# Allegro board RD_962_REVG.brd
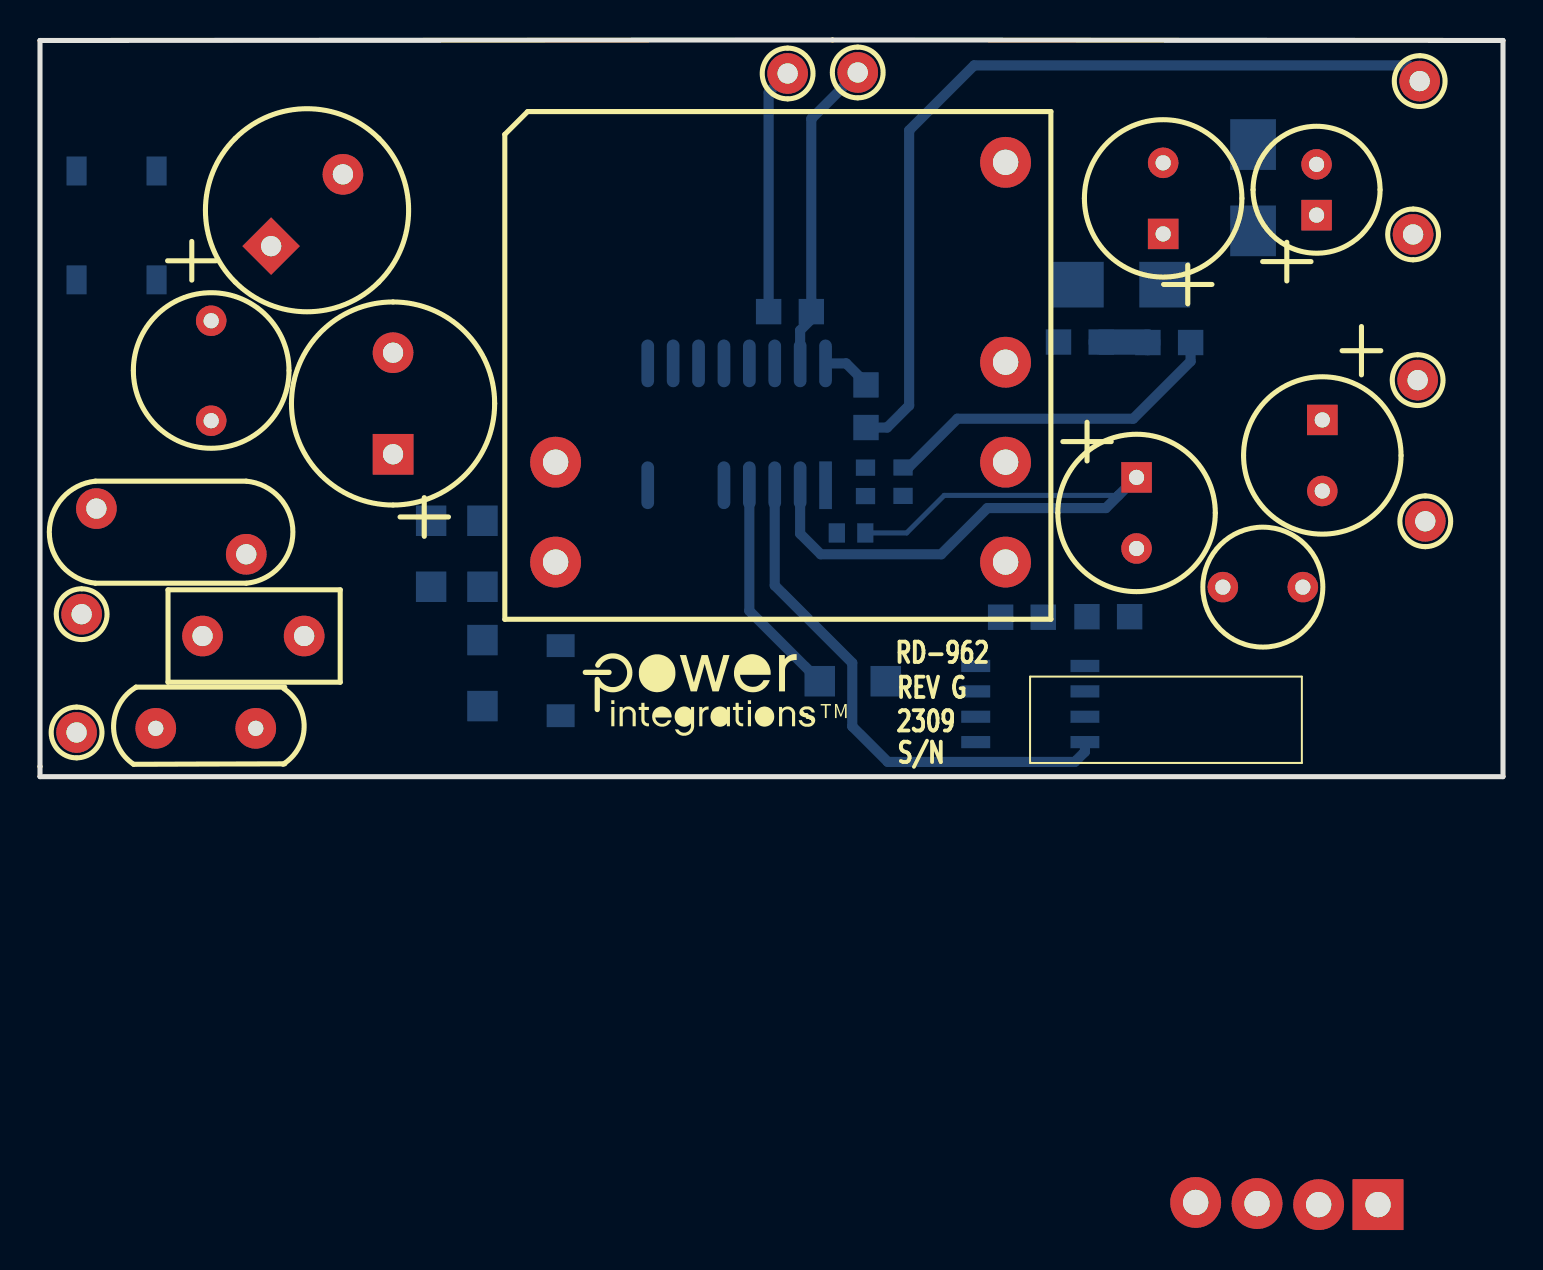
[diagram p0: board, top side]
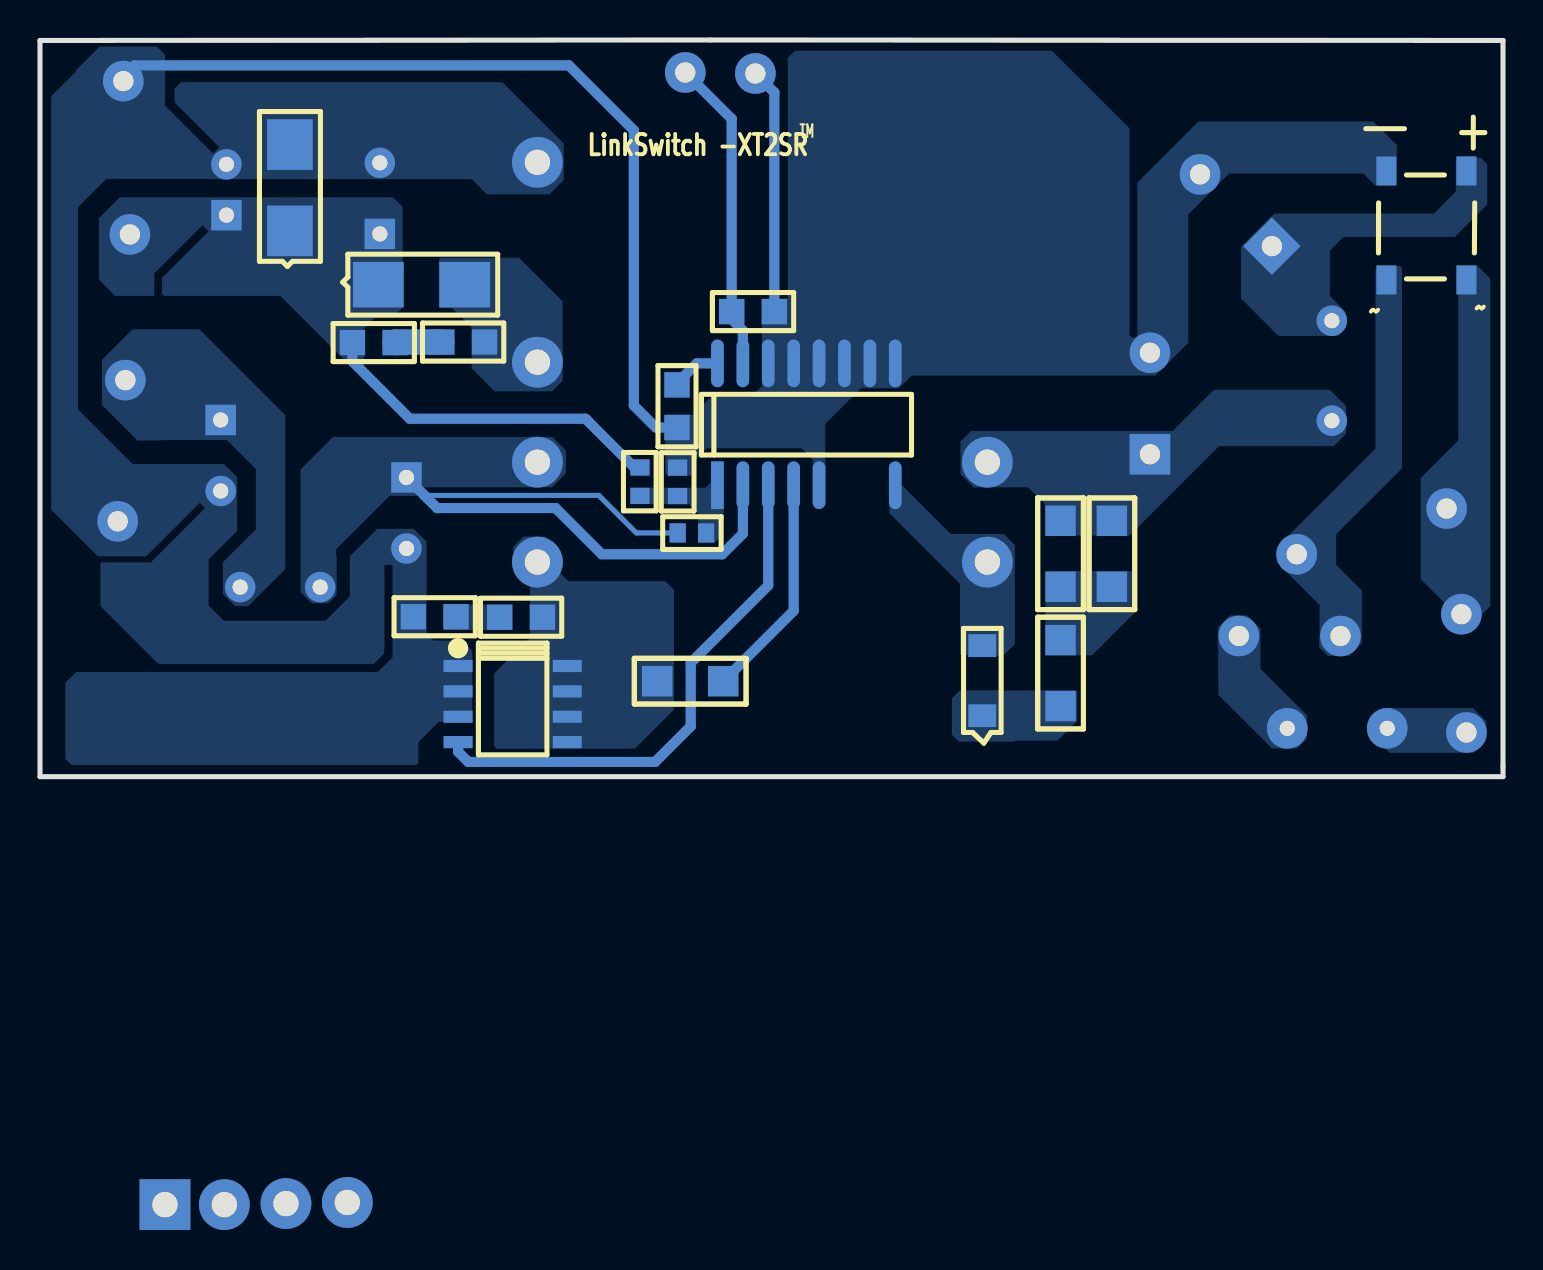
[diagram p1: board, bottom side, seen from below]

Outline 73.15 x 36.86 mm; copper layers: TOP, BOTTOM. Coordinates in mm from the lower left corner of the outline.
Outline path: 0,36.83 0,0 73.15,0 73.15,36.83 39.62,36.86 0,36.83

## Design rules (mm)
constraint set DEFAULT: min track width 0.508

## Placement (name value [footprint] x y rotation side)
BR1  ABS210-13  [PISMD_SOPA-4]  1.83 30.3 180 bottom
C1  15 uF  [PIPOLCAPCYLD400LS200040]  11.56 26.54 45 top
C2  15 uF  [PIPOLCAPCYLD400LS200040]  17.65 16.13 90 top
C3  1000 pF  [PISMC1206]  22.12 12.8 270 bottom
C4  4.7 uF  [PISMC0805]  41.3 19.6 270 bottom
C5  2.2 uF  [PISMC0805]  36.43 23.27 0 bottom
C6  1.5 nF  [PISMC0805]  52.35 8 0 bottom
C7  1000 uF  [PIPOLCAPCLYD320LS140030]  56.16 27.15 90 top
C9  100 uF  [PIPOLCAPCYLD250LS100030]  63.83 28.09 90 top
C10  680  uF  [PIPOLCAPCLYD320LS140030]  54.83 14.97 270 top
C11  680  uF  [PIPOLCAPCLYD320LS140030]  64.12 17.85 270 top
C12  1 nF  [PISMC0805]  55.4 21.72 0 bottom
D1  S1MLHRVG  [PI_SM_SOD-123_12]  26.04 3.05 90 bottom
D2  STPS2150A  [PISMDO214AC12]  56.24 24.61 180 bottom
F1  2 A  [PI_RST_MICROFUSE]  13.21 7.04 180 top
GND  BLK  [PITPKEYSTONE100X100]  37.38 35.18 0 top
GND1  BLK  [PITPKEYSTONE100X100]  68.99 34.8 0 top
GND2  BLK  [PITPKEYSTONE100X100]  69.27 12.78 0 top
L  BLK  [PITPKEYSTONE100X100]  1.83 2.21 0 top
L1  330 uH  [PICHOKETOKINVD345H453LS197D030]  8.56 22.81 270 top
L2  1.7 uH  [PICHOKE6MM2PIN4MMLSD030]  59.14 9.48 270 top
N  WHT  [PITPKEYSTONE100X100]  2.08 8.13 0 top
NOREF  -  []  27.15 6.6 0 top
NOREF#2  -  []  -140.04 52.68 0 top
NOREF#3  -  []  0.03 34.82 0 top
NOREF#4  -  []  -217.86 -146.33 0 top
NOREF#5  -  []  0 0 90 top
Q1  AO4264E  [PISMSO8]  52.25 5.54 270 bottom
R1  200 k  [PISMR1206]  19.56 12.8 270 bottom
R2  330  [PISMR1206]  22.12 6.83 270 bottom
R3  47  [PISMR1206]  38.99 4.78 0 bottom
R4  4.7  [PISMR0805]  48.03 7.98 0 bottom
R7  46.4 k  [PISMR0603]  41.27 12.19 180 bottom
R8  619 k  [PISMR0603]  43.15 15.47 270 bottom
R9  24.9 k  [PISMR0603]  41.27 14.04 90 bottom
R10  30  [PISMR0805]  50.93 21.74 0 bottom
RT1  2.5  [PI_RAD150X300LS200D030]  10.79 2.42 180 top
RV1  275 Vac  [PI_DISC_475X200LS295X90D040]  10.31 11.13 180 top
T1  EFD25  [PI_BOBBIN_EFD25_10P]  25.78 30.73 0 top
U1  LNK3773D  [PI_SMD_SO_14-16P_SHORT9-14]  39.28 14.58 180 bottom
UNK5V  RED  [PITPKEYSTONE100X100]  68.88 19.84 0 top
UNK12V  YEL  [PITPKEYSTONE100X100]  68.66 27.13 0 top
UVCC  WHT  [PITPKEYSTONE100X100]  40.89 35.23 0 top
VR1  SMAJ4743A-TP  [PISMDO214AC12]  60.66 27.3 90 bottom

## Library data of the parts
BR1 = DIODE BRIDGE_+~~-: alternate symbols: (pismd_SOPA-4a,pi_sm_soic4_slot)
C1 C2 = CAP POL: alternate symbols: (pipolcapclyd400x630ls200030h)
C3-C6 = CAP NP
C7 = CAP POL: alternate symbols: (pipolcapclyd320ls140d30h750)
C9 = CAP POL: alternate symbols: (pipolcapcyld250ls100030h)
C10 C11 = CAP POL
C12 = CAP NP: alternate symbols: (pismc0805_1)
D1 = DIODE
D2 = DIODE SCHOTTKY
F1 = FUSE: alternate symbols: (pirstmicrofusehoz)
GND GND1 GND2 N UNK5V UNK12V UVCC = TESTPOINT
L = TESTPOINT: alternate symbols: (TP_TH_CR2_D1_1)
L1 = INDUCTOR: alternate symbols: (pichoketokinvd345h453ls197d030H)
L2 = INDUCTOR
Q1 = FET_P_SGD_123_4_5678
R1-R4 R7-R10 = R
RT1 = THERMISTOR: alternate symbols: (pirad400x300ls200040_h)
RV1 = VARISTOR
T1 = BEFD25_10P/GENERIC
U1 = LNKXT2-SR2
VR1 = DIODE_ZENER

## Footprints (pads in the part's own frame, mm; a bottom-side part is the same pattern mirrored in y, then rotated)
PI_BOBBIN_EFD25_10P
  rect 2.54x2.54 hole 1.27: 1(41.123,-52.146)
  round 2.54 hole 1.27: 2(38.153,-52.146) 3(32.004,-52.037) 4(0,-15.001) 5(0,-20) 6(22.499,-20) 7(22.499,-15.001) 8(22.499,-10) 9(35.072,-52.093) 10(22.499,0)
PI_DISC_475X200LS295X90D040
  round 2.032 hole 1.016: 1(0,0) 2(7.493,-2.286)
PI_RAD150X300LS200D030
  round 2.032 hole 0.762: 1(0,0) 2(5,0)
PI_RST_MICROFUSE
  round 2.032 hole 1.016: 1(0,0) 2(5.08,0)
PI_SM_SOD-123_12
  rect 1.143x1.397 smd: 1(0,0) 2(3.505,0)
PI_SMD_SO_14-16P_SHORT9-14
  rect 0.635x2.388 smd: 1(0,0)
  oval 0.635x2.388 smd: 2(1.27,0) 3(2.54,0) 4(3.81,0) 5(5.08,0) 8(8.89,0) 9(8.89,6.096) 10(7.62,6.096) 11(6.35,6.096) 12(5.08,6.096) 13(3.81,6.096) 14(2.54,6.096) 15(1.27,6.096) 16(0,6.096)
PICHOKE6MM2PIN4MMLSD030
  round 1.524 hole 0.762: 1(0,0) 2(0,4)
PICHOKETOKINVD345H453LS197D030
  round 1.524 hole 0.762: 1(0,0) 2(5.001,0)
PIPOLCAPCLYD320LS140030
  rect 1.524x1.524 hole 0.762: 1(0,0)
  round 1.524 hole 0.762: 2(3.556,0)
PIPOLCAPCYLD250LS100030
  rect 1.524x1.524 hole 0.762: 1(0,0)
  round 1.524 hole 0.762: 2(2.54,0)
PIPOLCAPCYLD400LS200040
  rect 2.032x2.032 hole 1.016: 1(0,0)
  round 2.032 hole 1.016: 2(5.08,0)
PISMC0805
  rect 1.27x1.27 smd: 1(0,0) 2(2.134,0)
PISMC1206
  rect 1.524x1.524 smd: 1(0,0) 2(3.302,0)
PISMD_SOPA-4
  rect 1.001x1.45 smd: 1(0,0) 2(0,-5.451) 3(-4,-5.451) 4(-4,0)
PISMDO214AC12
  rect 2.54x2.286 smd: 1(0,0) 2(4.318,0)
PISMR0603
  rect 0.813x0.965 smd: 1(0,0) 2(1.422,0)
PISMR0805
  rect 1.27x1.27 smd: 1(0,0) 2(2.134,0)
PISMR1206
  rect 1.524x1.524 smd: 1(0,0) 2(3.302,0)
PISMSO8
  rect 0.61x1.448 smd: 1(0,0) 2(1.27,0) 3(2.54,0) 4(3.81,0) 5(3.81,5.461) 6(2.54,5.461) 7(1.27,5.461) 8(0,5.461)
PITPKEYSTONE100X100
  round 2.032 hole 1.016: 1(0,0)

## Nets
0: BR1.4 C1.2 C2.2 C4.2 C5.1 C6.2 C7.2 C9.2 C10.2 C11.2 GND.1 GND1.1 GND2.1 Q1.1 Q1.2 Q1.3(S3) R9.2 T1.10 U1.5 U1.9 U1.10 U1.11 U1.12 U1.13 U1.14 VR1.2
N11170642: C2.1 C3.1 L1.2 R1.1 T1.4
N11170782: BR1.1 C1.1 L1.1
N11170894: C11.1 L2.2 UNK5V.1
N11170962: C3.2 R1.2 R2.1
N11171108: Q1.5 Q1.6 Q1.7 Q1.8 R3.2 R4.1 T1.6
N11171534: R3.1 U1.4
N11182138: Q1.4 U1.3
N11187578: C7.1 C9.1 C12.2 D2.1 R8.1 UNK12V.1 VR1.1
N11188222: C5.2 U1.15 UVCC.1
N11194985: BR1.2 N.1 RV1.2
N11194992: BR1.3 F1.2 RV1.1
N11203470: F1.1 RT1.1
N11204081: R7.2 R8.2 R9.1 U1.1
N11210341: D2.2 R10.1 T1.8
N11218878: C10.1 L2.1 R7.1 T1.7 U1.2
N11259707: C6.1 R4.2
N11261351: D1.2 T1.5 U1.8
N11265143: C4.1 U1.16
N11281825: D1.1 R2.2
N11293270: L.1 RT1.2
N11294619: C12.1 R10.2

Pads without a net: T1 1 2 3 9

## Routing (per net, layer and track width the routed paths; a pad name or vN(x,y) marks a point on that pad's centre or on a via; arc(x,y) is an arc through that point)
0: length 56.6
  BOTTOM w0.508: C4.2 42.36,17.47 43.46,18.57 43.46,32.33 46.71,35.59 68.43,35.59 68.99,35.03 GND1.1 69.57,34.8 ; C5.1 36.43,34.23 GND.1
N11171534: length 11.6
  BOTTOM w0.508: R3.1 38.84,4.62 38.84,4.93 35.47,8.3 U1.4
N11182138: length 26.7
  BOTTOM w0.508: U1.3 36.74,9.57 40.61,5.69 40.61,2.51 42.39,0.74 51.74,0.74 52.25,1.24 Q1.4
N11187578: length 17.5
  BOTTOM w0.508: C12.2 57.53,20.78 54.66,17.91 45.87,17.91 43.43,15.47 R8.1
N11188222: length 15.7
  BOTTOM w0.508: UVCC.1 38.57,32.91 C5.2 38.57,22.89 38.01,22.33 U1.15
N11218878: length 34.8
  BOTTOM w0.254: R7.1 43.33,12.19 45.21,14.07 53.93,14.07 ; 53.3,13.44 53.24,13.39
  BOTTOM w0.508: U1.2 38.01,12.16 39.04,11.13 45.06,11.13 47.37,13.44 53.3,13.44 C10.1
N11265143: length 2.5
  BOTTOM w0.508: U1.16 40.31,20.68 41.3,19.68 C4.1
N11294619: length 2.3
  BOTTOM w1.27: R10.2 55.37,21.74 C12.1

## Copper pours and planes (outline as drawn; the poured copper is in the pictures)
0 on BOTTOM: 37.06,19.53 37.59,19 39.55,19 39.57,19.02 40.49,18.11 41.94,18.11 41.88,18.06 41.88,15.19 41.76,15.06 40.44,15.06 40.34,15.16 40.34,15.9 39.8,16.43 35.08,16.43 34.52,15.88 34.52,13.69 34.26,13.44 34.06,13.44 33.88,13.61 33.88,17.65 32.11,19.43 30.2,19.43 29.57,20.07 17.37,20.07 15.74,21.7 15.74,28.13 13.69,30.18 6.96,30.18 6.88,30.1 6.88,30.07 6.4,29.59 5.31,29.59 5.31,31.6 6.49,32.78 15.23,32.78 18.29,29.72 18.29,22.07 18.39,21.97 18.57,21.97 18.67,22.07 18.67,32.44 22.56,36.32 35.41,36.32 35.76,35.97 35.76,23.98 35.84,23.9 37.06,23.9
0 on BOTTOM: 67.31,36.53 70.17,36.53 71.36,35.33 71.36,35.27 72.59,34.04 72.59,13.36 70.26,11.02 67.84,11.02 65.18,13.69 65.15,13.69 64.9,13.44 67.61,10.72 70.13,10.72 70.13,8.53 67.23,5.64 56.46,5.64 55.94,6.16 55.94,6.26 55.93,6.27 55.93,10.59 55.52,10.59 55.52,5.97 56.26,5.23 71.35,5.23 71.88,4.7 71.88,0.89 71.58,0.58 54.33,0.58 54.23,0.69 54.23,1.73 53.21,2.74 51.54,2.74 51.54,6.3 52.04,6.81 53.47,6.81 53.82,7.16 53.82,11.76 54.46,12.4 56.29,12.4 57.66,11.02 57.66,9.02 58.88,7.8 63.96,7.8 64.72,8.56 64.72,10.87 63.3,12.29 63.3,14.99 63.96,15.65 68.53,15.65 71.25,18.36 71.25,28.5 69.84,29.91 64.86,29.91 64.85,29.9 51.56,29.9 50.8,29.13 47.68,29.13 46.96,29.84 46.96,31.67 50.04,34.75 66.09,34.75 66.42,34.42 66.42,33.73 64.19,31.5 64.49,31.19 64.52,31.19 66.9,33.58 66.9,36.12
N11170642 on BOTTOM: 26.59,17.3 27.13,16.76 27.13,15.14 26.47,14.48 23.75,14.48 22.89,13.61 22.89,12.27 22.68,12.06 18.67,12.06 14.2,16.54 8.46,16.54 7.85,17.14 7.85,18.54 8.66,19.35 14.45,19.35 16.51,17.3
N11170782 on BOTTOM: 8.26,22.05 7.87,22.43 7.87,23.27 8.66,24.05 8.66,26.31 7.98,27 2.41,27 0.79,28.63 0.79,30.63 1.12,30.96 2.26,30.96 2.36,30.86 2.36,29.26 3.45,28.17 11.43,28.17 13.1,26.5 13.1,23.92 11.23,22.05
N11170894 on BOTTOM: 64.01,9.14 64.01,10.72 62.36,12.37 62.36,15.39 63.8,16.84 67.08,16.84 67.11,16.81 68.28,16.81 70.05,18.59 70.05,20.85 68.53,22.38 65.18,22.38 60.88,18.08 60.88,10.39 62.74,8.53 63.4,8.53
N11170962 on BOTTOM: 22.89,10.13 22.73,10.29 18.62,10.29 18.36,10.03 18.36,8.26 20.55,6.07 22.86,6.07 22.89,6.1
N11171108 on BOTTOM: 41.45,3.35 41.45,9.35 41.88,9.78 46.74,9.78 47.14,10.19 47.14,11.28 47.88,12.01 48.97,12.01 49.49,11.49 49.49,10.39 49.51,10.37 48.64,9.5 48.64,6.96 50.44,5.16 50.44,1.52 50.32,1.4 43.41,1.4
N11187578 on BOTTOM: 69.16,28.98 70.21,27.94 70.21,24.87 69.39,24.05 67.44,24.05 67.44,25.17 65.02,27.58 64.74,27.3 64.74,27.25 67.01,24.99 67.06,24.99 67.06,24.16 66.95,24.05 61.14,24.05 57.53,20.45 57.12,20.45 56.95,20.62 56.95,22.43 56.31,23.06 55.42,23.06 55.02,23.47 55.02,28.5 55.5,28.98
N11194985 on BOTTOM: 0.64,24.92 1.27,25.55 2.24,25.55 2.24,16.81 4.11,14.94 4.11,9.88 2.11,7.87 1.3,7.87 0.64,8.53
N11194992 on BOTTOM: 5.05,25.45 5.16,25.55 6.2,25.55 6.38,25.37 6.38,16.41 11.34,11.44 11.33,11.43 11.33,10.74 9.19,8.61 9.17,8.61 9.17,6.99 9.19,6.96 9.19,6.48 8.76,6.05 7.7,6.05 7.06,6.68 7.06,9.32 8.34,10.6 8.34,12.13 5.05,15.42
N11203470 on BOTTOM: 12.13,7.41 12.79,8.07 13.65,8.07 14.26,7.46 14.26,6.38 14.24,6.36 14.24,4.93 14.23,4.92 14.23,4.1 11.54,1.41 10.3,1.41 9.8,1.91 9.8,3.07 12.13,5.4
N11204081 on BOTTOM: 39.6,14.73 39.88,14.45 43.51,14.45 43.61,14.35 43.61,13.77 43.48,13.64 40.72,13.64 40.23,13.16 40.23,11.86 40.08,11.71 39.42,11.71 38.96,12.17 38.96,15.6 39.14,15.77 39.45,15.77 39.6,15.62
N11210341 on BOTTOM: 53.14,25.96 49.2,25.96 47.02,23.77 47.02,19.81 47.55,19.28 50.42,19.28 51.56,20.42 51.56,22.45 52.63,23.52 53.19,23.52 53.19,25.91
N11218878 on BOTTOM: 58.5,16.99 60.12,15.37 60.12,9.23 59.56,8.67 58.74,8.67 58.32,9.09 58.32,10.97 58.34,11 58.34,11.38 55.68,14.05 53.95,14.05 53.92,14.02 53.9,14.05 53.9,14.5 53.87,14.48 47.55,14.48 46.86,15.16 46.86,16.33 47.52,16.99
N11259707 on BOTTOM: 49.56,8.43 49.73,8.61 52.88,8.61 52.98,8.51 52.98,7.39 52.93,7.34 49.61,7.34 49.56,7.39
N11261351 on BOTTOM: 30.12,14.66 30.12,15.62 30.2,15.7 30.61,15.7 30.68,15.62 30.68,13.18 27.15,9.65 27.15,6.15 27.08,6.07 24.97,6.07 24.41,6.63 24.41,11.58 24.97,12.14 27.61,12.14
N11281825 on BOTTOM: 25.06,4.32 27.15,4.32 27.56,3.91 27.56,2.11 27.2,1.75 24.43,1.75 24.38,1.8 22.28,1.8 21.29,2.79 21.29,4.24 21.36,4.32 21.37,4.31 25.05,4.31
N11293270 on BOTTOM: 0.84,2.77 1.5,3.43 5.82,3.43 6.43,2.82 6.43,1.96 5.66,1.19 1.47,1.19 0.84,1.83

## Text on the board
Ref Des/Silkscreen Bottom: TM | LinkSwitch -XT2SR
Ref Des/Silkscreen Top: RD-962 | 2309 | REV G | S/N
FAB_NOTES: 13   MATERIAL FR4 COPPER 2oz THICKNESS 0.062" | PLEASE DELETE THESE PINS
User.7: FIGURE | FINISHED_SIZE | 30.0 | 40.0 | 50.0 | DRILL CHART: TOP to BOTTOM | ALL UNITS ARE IN MILS | TOLERANCE_DRILL | +0.0/-0.0 | +3.0/-3.0 | PLATED | QTY | 2 | 6 | 4 | 12 | 10
